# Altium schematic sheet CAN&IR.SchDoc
size A4; Revision: B.2
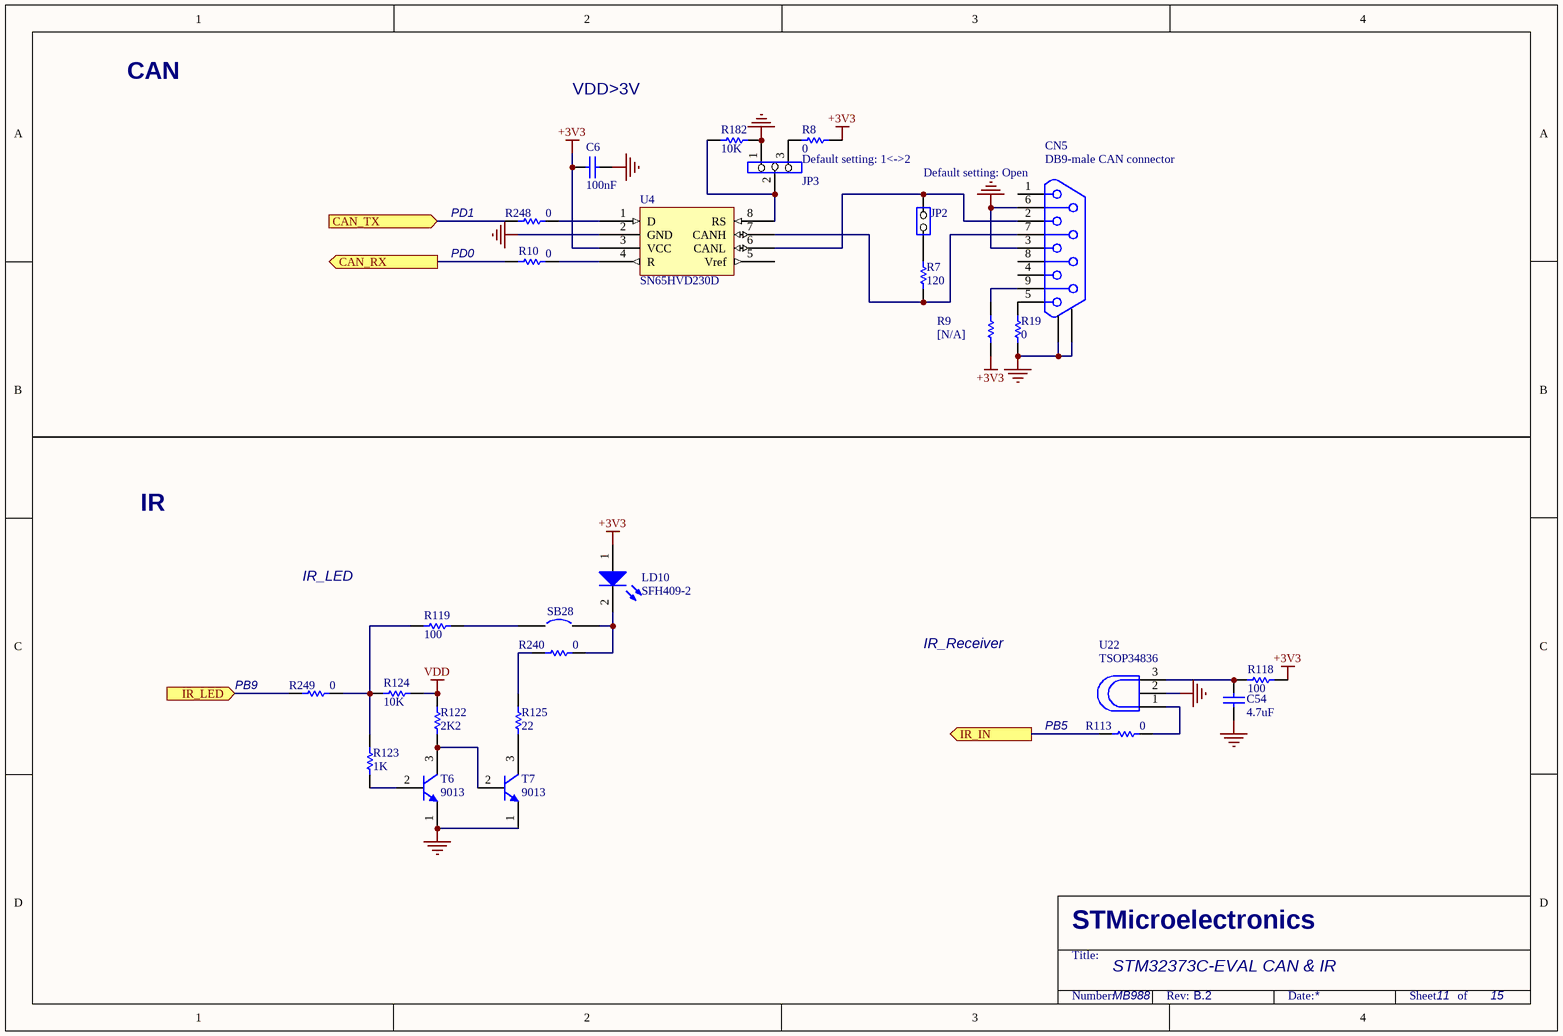
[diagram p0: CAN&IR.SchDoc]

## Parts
C6  100nF  [0603C]
C54  4.7uF  [0603C]
CN5  DB9-male CAN connector  [DB9/M]
JP2  (no value)  [SIP2]
JP3  (no value)  [SIP3]
LD10  SFH409-2  [D0.1L]
R7  120  [0603R]
R8  0  [0603R]
R9  [N/A]  [0603R]
R10  0  [0603R]
R19  0  [0603R]
R113  0  [0603R]
R118  100  [0603R]
R119  100  [0603R]
R122  2K2  [0603R]
R123  1K  [0603R]
R124  10K  [0603R]
R125  22  [0603R]
R182  10K  [0603R]
R240  0  [0603R]
R248  0  [0603R]
R249  0  [0603R]
SB28  (no value)  [JP2_SMD]
T6  9013  [SOT-23]
T7  9013  [SOT-23]
U4  SN65HVD230D  [SO8]
U22  TSOP34836  [TSOP348]

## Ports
CAN_RX (out), CAN_TX (in), IR_IN (out), IR_LED (in)

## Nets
+3V3: C6.2 LD10.1(A) R8.2 R9.1 R118.2 U4.3(VCC)
GND: C6.1 C54.2 CN5.0 CN5.3 CN5.6 JP3.1 R19.1 R182.2 T6.1(E) T7.1(E) U4.2(GND) U22.2(GND)
VDD: R122.2 R124.1
CAN_RX: R10.1 ; port CAN_RX
CAN_TX: R248.2 ; port CAN_TX
IR_IN: R113.1 ; port IR_IN
IR_LED: R249.2 ; port IR_LED
NetC54_1: C54.1 R118.1 U22.3(Vs)
NetCN5_2: CN5.2 JP2.2(NO) U4.6(CANL)
NetCN5_5: CN5.5 R19.2
NetCN5_7: CN5.7 R7.1 U4.7(CANH)
NetCN5_9: CN5.9 R9.2
NetJP2_1: JP2.1(COMMON) R7.2
NetJP3_2: JP3.2 R182.1 U4.8(RS)
NetJP3_3: JP3.3 R8.1
NetLD10_2: LD10.2(K) R240.2 SB28.2
NetR10_2: R10.2 U4.4(R)
NetR113_2: R113.2 U22.1(OUT)
NetR119_1: R119.1 SB28.1
NetR119_2: R119.2 R123.1 R124.2 R249.1
NetR122_1: R122.1 T6.3(C) T7.2(B)
NetR123_2: R123.2 T6.2(B)
NetR125_1: R125.1 T7.3(C)
NetR125_2: R125.2 R240.1
NetR248_1: R248.1 U4.1(D)

Not connected (* = marked no-connect by the designer): CN5 1 4 8; U4 5(Vref)

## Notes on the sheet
- CAN
- VDD>3V
- Default setting: 1<->2
- (near CN5) Default setting: Open
- PD1
- PD0
- IR
- IR_LED
- IR_Receiver
- (near R249) PB9
- PB5
- STM32373C-EVAL CAN & IR
- MB988
- 11
- 15

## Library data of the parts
C6 = CAP: Capacitor
C54 = Cap: Capacitor; Value: 10nF
CN5 = DB9
JP2 = JP2
JP3 = Jumper3
LD10 = LED2: Typical RED, GREEN, YELLOW, AMBER GaAs LED
R7-R9 R19 R182 = res1: Resistor; Value: 1K
R10 R113 R118 R119 R122 R124 R125 R240 R248 R249 = Res1: Resistor; Value: 1K
R123 = Res1: Resistor
SB28 = Circuit Breaker
T6 T7 = NPN: NPN Bipolar Transistor; Code - JEDEC: TO-226-AA
U22 = TSOP34838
